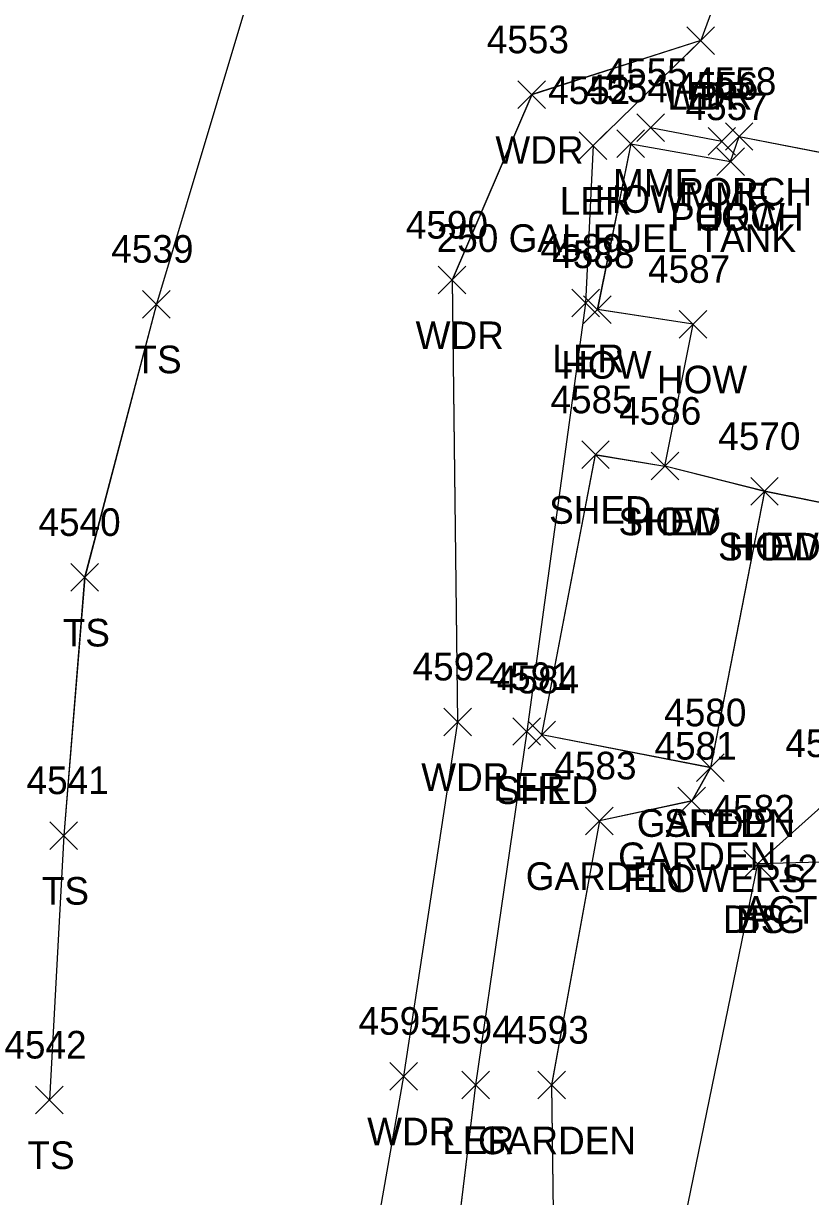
# Model space of a CAD drawing. Extents: x 1554668 to 1563881, y 831386 to 834374.
# Drawn here: x 1562370.9 to 1562427.9, y 833776.4 to 833861.3 of the extents above; entities that cross this region are included whole.
import ezdxf

# ---------------------------------------------------------------- set-up
doc = ezdxf.new("R2010")
doc.units = 0
for name, color, linetype in [('D_C', 7, 'Continuous'), ('L_A', 7, 'Continuous'), ('L_C', 7, 'Continuous'), ('L_I', 7, 'Continuous'), ('L_TIC', 7, 'Continuous'), ('LAPB', 7, 'Continuous'), ('LARO', 7, 'Continuous'), ('LAWA', 7, 'Continuous'), ('LBC', 7, 'Continuous'), ('LBF', 7, 'Continuous'), ('LDEFAULT', 7, 'Continuous'), ('LELB', 7, 'Continuous'), ('R_A', 7, 'Continuous'), ('R_I', 7, 'Continuous'), ('R_TIC', 7, 'Continuous'), ('RDG', 7, 'Continuous')]:
    doc.layers.add(name, color=color, linetype=linetype)

msp = doc.modelspace()

# ---------------------------------------------------------------- linework, layer by layer
at = {"layer": 'L_TIC'}
for points in [[(1562418.963, 833859.015), (1562420.963, 833861.015)], [(1562420.963, 833859.015), (1562418.963, 833861.015)], [(1562418.963, 833859.015), (1562420.963, 833861.015)], [(1562420.963, 833859.015), (1562418.963, 833861.015)], [(1562406.739, 833855.098), (1562408.739, 833857.098)], [(1562408.739, 833855.098), (1562406.739, 833857.098)], [(1562415.337, 833852.719), (1562417.337, 833854.719)], [(1562417.337, 833852.719), (1562415.337, 833854.719)], [(1562420.495, 833851.73), (1562422.495, 833853.73)], [(1562422.495, 833851.73), (1562420.495, 833853.73)], [(1562421.749, 833852.075), (1562423.749, 833854.075)], [(1562423.749, 833852.075), (1562421.749, 833854.075)], [(1562411.178, 833851.42), (1562413.178, 833853.42)], [(1562413.178, 833851.42), (1562411.178, 833853.42)], [(1562413.902, 833851.549), (1562415.902, 833853.549)], [(1562415.902, 833851.549), (1562413.902, 833853.549)], [(1562413.902, 833851.549), (1562415.902, 833853.549)], [(1562415.902, 833851.549), (1562413.902, 833853.549)], [(1562421.129, 833850.258), (1562423.129, 833852.258)], [(1562423.129, 833850.258), (1562421.129, 833852.258)], [(1562421.129, 833850.258), (1562423.129, 833852.258)], [(1562423.129, 833850.258), (1562421.129, 833852.258)], [(1562400.97, 833841.686), (1562402.97, 833843.686)], [(1562402.97, 833841.686), (1562400.97, 833843.686)], [(1562379.572, 833839.938), (1562381.572, 833841.938)], [(1562381.572, 833839.938), (1562379.572, 833841.938)], [(1562410.639, 833840.014), (1562412.639, 833842.014)], [(1562412.639, 833840.014), (1562410.639, 833842.014)], [(1562411.484, 833839.549), (1562413.484, 833841.549)], [(1562413.484, 833839.549), (1562411.484, 833841.549)], [(1562411.484, 833839.549), (1562413.484, 833841.549)], [(1562413.484, 833839.549), (1562411.484, 833841.549)], [(1562418.412, 833838.485), (1562420.412, 833840.485)], [(1562420.412, 833838.485), (1562418.412, 833840.485)], [(1562411.352, 833829.045), (1562413.352, 833831.045)], [(1562413.352, 833829.045), (1562411.352, 833831.045)], [(1562416.373, 833828.217), (1562418.373, 833830.217)], [(1562418.373, 833828.217), (1562416.373, 833830.217)], [(1562416.373, 833828.217), (1562418.373, 833830.217)], [(1562418.373, 833828.217), (1562416.373, 833830.217)], [(1562423.584, 833826.394), (1562425.584, 833828.394)], [(1562425.584, 833826.394), (1562423.584, 833828.394)], [(1562423.584, 833826.394), (1562425.584, 833828.394)], [(1562425.584, 833826.394), (1562423.584, 833828.394)], [(1562374.38, 833820.165), (1562376.38, 833822.165)], [(1562376.38, 833820.165), (1562374.38, 833822.165)], [(1562401.375, 833809.707), (1562403.375, 833811.707)], [(1562403.375, 833809.707), (1562401.375, 833811.707)], [(1562406.378, 833809.012), (1562408.378, 833811.012)], [(1562408.378, 833809.012), (1562406.378, 833811.012)], [(1562407.468, 833808.768), (1562409.468, 833810.768)], [(1562409.468, 833808.768), (1562407.468, 833810.768)], [(1562419.671, 833806.389), (1562421.671, 833808.389)], [(1562421.671, 833806.389), (1562419.671, 833808.389)], [(1562419.671, 833806.389), (1562421.671, 833808.389)], [(1562421.671, 833806.389), (1562419.671, 833808.389)], [(1562418.318, 833803.98), (1562420.318, 833805.98)], [(1562420.318, 833803.98), (1562418.318, 833805.98)], [(1562411.633, 833802.545), (1562413.633, 833804.545)], [(1562413.633, 833802.545), (1562411.633, 833804.545)], [(1562372.867, 833801.48), (1562374.867, 833803.48)], [(1562374.867, 833801.48), (1562372.867, 833803.48)], [(1562423.084, 833799.427), (1562425.084, 833801.427)], [(1562425.084, 833799.427), (1562423.084, 833801.427)], [(1562397.463, 833784.065), (1562399.463, 833786.065)], [(1562399.463, 833784.065), (1562397.463, 833786.065)], [(1562402.673, 833783.437), (1562404.673, 833785.437)], [(1562404.673, 833783.437), (1562402.673, 833785.437)], [(1562408.176, 833783.422), (1562410.176, 833785.422)], [(1562410.176, 833783.422), (1562408.176, 833785.422)], [(1562371.826, 833782.346), (1562373.826, 833784.346)], [(1562373.826, 833782.346), (1562371.826, 833784.346)]]:
    msp.add_lwpolyline(points, dxfattribs=at)
at = {"layer": 'LAPB'}
for points in [[(1562420.669, 833807.396), (1562419.316, 833804.986), (1562412.633, 833803.558), (1562409.177, 833784.435), (1562409.39, 833767.848), (1562405.557, 833759.29), (1562400.567, 833759.011)], [(1562420.669, 833807.396), (1562419.316, 833804.986), (1562412.633, 833803.558), (1562409.177, 833784.435), (1562409.39, 833767.848), (1562405.557, 833759.29), (1562400.567, 833759.011)], [(1562420.669, 833807.396), (1562419.316, 833804.986), (1562412.633, 833803.558), (1562409.177, 833784.435), (1562409.39, 833767.848), (1562405.557, 833759.29), (1562400.567, 833759.011)], [(1562420.671, 833807.389), (1562419.318, 833804.98), (1562412.633, 833803.545), (1562409.176, 833784.422), (1562409.391, 833767.84), (1562405.556, 833759.278), (1562400.568, 833759.003)]]:
    msp.add_lwpolyline(points, dxfattribs=at)
at = {"layer": 'LARO'}
for points in [[(1562419.963, 833860.015), (1562412.178, 833852.42), (1562411.639, 833841.014), (1562407.378, 833810.012), (1562403.673, 833784.437), (1562400.568, 833759.003), (1562399.074, 833758.901), (1562395.998, 833760.121), (1562387.534, 833736.965), (1562384.152, 833724.079), (1562381.399, 833714.569), (1562372.959, 833681.502), (1562364.479, 833661.333), (1562357.279, 833645.473), (1562345.403, 833619.618), (1562327.126, 833615.39), (1562315.305, 833599.808)], [(1562419.966, 833860.023), (1562412.181, 833852.429), (1562411.638, 833841.024), (1562407.377, 833810.024), (1562403.672, 833784.446), (1562400.567, 833759.011), (1562399.073, 833758.91), (1562395.997, 833760.128), (1562387.531, 833736.972), (1562384.152, 833724.088), (1562381.4, 833714.581), (1562372.955, 833681.511), (1562364.484, 833661.338), (1562357.283, 833645.478), (1562345.401, 833619.623), (1562327.128, 833615.397), (1562315.31, 833599.816)], [(1562419.966, 833860.023), (1562412.181, 833852.429), (1562411.638, 833841.024), (1562407.377, 833810.024), (1562403.672, 833784.446), (1562400.567, 833759.011), (1562399.073, 833758.91), (1562395.997, 833760.128), (1562387.531, 833736.972), (1562384.152, 833724.088), (1562381.4, 833714.581), (1562372.955, 833681.511), (1562364.484, 833661.338), (1562357.283, 833645.478), (1562345.401, 833619.623), (1562327.128, 833615.397), (1562315.31, 833599.816)], [(1562419.966, 833860.023), (1562412.181, 833852.429), (1562411.638, 833841.024), (1562407.377, 833810.024), (1562403.672, 833784.446), (1562400.567, 833759.011), (1562399.073, 833758.91), (1562395.997, 833760.128), (1562387.531, 833736.972), (1562384.152, 833724.088), (1562381.4, 833714.581), (1562372.955, 833681.511), (1562364.484, 833661.338), (1562357.283, 833645.478), (1562345.401, 833619.623), (1562327.128, 833615.397), (1562315.31, 833599.816)]]:
    msp.add_lwpolyline(points, dxfattribs=at)
at = {"layer": 'LAWA'}
for points in [[(1562378.208, 833932.425), (1562389.846, 833942.302), (1562394.252, 833938.943), (1562408.716, 833937.781), (1562415.125, 833914.02), (1562415.715, 833894.974), (1562418.032, 833878.589), (1562423.871, 833870.615), (1562419.966, 833860.023), (1562407.74, 833856.104), (1562401.969, 833842.691), (1562402.374, 833810.713), (1562398.461, 833785.078), (1562394.034, 833759.91)], [(1562378.208, 833932.425), (1562389.846, 833942.302), (1562394.252, 833938.943), (1562408.716, 833937.781), (1562415.125, 833914.02), (1562415.715, 833894.974), (1562418.032, 833878.589), (1562423.871, 833870.615), (1562419.966, 833860.023), (1562407.74, 833856.104), (1562401.969, 833842.691), (1562402.374, 833810.713), (1562398.461, 833785.078), (1562394.034, 833759.91)], [(1562378.208, 833932.425), (1562389.846, 833942.302), (1562394.252, 833938.943), (1562408.716, 833937.781), (1562415.125, 833914.02), (1562415.715, 833894.974), (1562418.032, 833878.589), (1562423.871, 833870.615), (1562419.966, 833860.023), (1562407.74, 833856.104), (1562401.969, 833842.691), (1562402.374, 833810.713), (1562398.461, 833785.078), (1562394.034, 833759.91)], [(1562378.208, 833932.42), (1562389.848, 833942.294), (1562394.25, 833938.94), (1562408.715, 833937.778), (1562415.128, 833914.011), (1562415.718, 833894.966), (1562418.033, 833878.583), (1562423.869, 833870.607), (1562419.963, 833860.015), (1562407.739, 833856.098), (1562401.97, 833842.686), (1562402.375, 833810.707), (1562398.463, 833785.065), (1562394.036, 833759.898)]]:
    msp.add_lwpolyline(points, dxfattribs=at)
at = {"layer": 'LBC'}
for points in [[(1562414.901, 833852.555), (1562412.483, 833840.561)], [(1562414.901, 833852.555), (1562412.483, 833840.561)], [(1562414.901, 833852.555), (1562412.483, 833840.561)], [(1562414.902, 833852.549), (1562412.484, 833840.549)], [(1562414.901, 833852.555), (1562422.132, 833851.267)], [(1562414.901, 833852.555), (1562422.132, 833851.267)], [(1562414.901, 833852.555), (1562422.132, 833851.267)], [(1562414.902, 833852.549), (1562422.129, 833851.258)], [(1562445.075, 833842.183), (1562441.39, 833824.008), (1562424.584, 833827.399), (1562417.372, 833829.227), (1562419.41, 833839.49), (1562412.483, 833840.561)], [(1562445.075, 833842.183), (1562441.39, 833824.008), (1562424.584, 833827.399), (1562417.372, 833829.227), (1562419.41, 833839.49), (1562412.483, 833840.561)], [(1562445.075, 833842.183), (1562441.39, 833824.008), (1562424.584, 833827.399), (1562417.372, 833829.227), (1562419.41, 833839.49), (1562412.483, 833840.561)], [(1562445.076, 833842.176), (1562441.389, 833824.003), (1562424.584, 833827.394), (1562417.373, 833829.217), (1562419.412, 833839.485), (1562412.484, 833840.549)], [(1562424.584, 833827.399), (1562420.669, 833807.396), (1562408.466, 833809.775), (1562412.35, 833830.05), (1562417.372, 833829.227)], [(1562424.584, 833827.399), (1562420.669, 833807.396), (1562408.466, 833809.775), (1562412.35, 833830.05), (1562417.372, 833829.227)], [(1562424.584, 833827.399), (1562420.669, 833807.396), (1562408.466, 833809.775), (1562412.35, 833830.05), (1562417.372, 833829.227)], [(1562424.584, 833827.394), (1562420.671, 833807.389), (1562408.468, 833809.768), (1562412.352, 833830.045), (1562417.373, 833829.217)]]:
    msp.add_lwpolyline(points, dxfattribs=at)
at = {"layer": 'LBF'}
for points in [[(1562422.129, 833851.258), (1562422.749, 833853.075), (1562435.102, 833850.67), (1562440.566, 833849.466), (1562446.365, 833848.39), (1562445.076, 833842.176)], [(1562422.132, 833851.267), (1562422.749, 833853.081), (1562435.102, 833850.678), (1562440.566, 833849.476), (1562446.364, 833848.399), (1562445.075, 833842.183)], [(1562422.132, 833851.267), (1562422.749, 833853.081), (1562435.102, 833850.678), (1562440.566, 833849.476), (1562446.364, 833848.399), (1562445.075, 833842.183)], [(1562422.132, 833851.267), (1562422.749, 833853.081), (1562435.102, 833850.678), (1562440.566, 833849.476), (1562446.364, 833848.399), (1562445.075, 833842.183)]]:
    msp.add_lwpolyline(points, dxfattribs=at)
at = {"layer": 'LDEFAULT'}
for points in [[(1562416.337, 833853.726), (1562421.497, 833852.739)], [(1562416.337, 833853.726), (1562421.497, 833852.739)], [(1562416.337, 833853.726), (1562421.497, 833852.739)], [(1562416.337, 833853.719), (1562421.495, 833852.73)]]:
    msp.add_lwpolyline(points, dxfattribs=at)
at = {"layer": 'LELB'}
for points in [[(1562394.252, 833938.943), (1562392.007, 833921.885), (1562390.327, 833902.359), (1562390.311, 833886.596), (1562389.314, 833870.102), (1562380.568, 833840.943), (1562375.377, 833821.168), (1562373.869, 833802.489), (1562372.825, 833783.352)], [(1562394.252, 833938.943), (1562392.007, 833921.885), (1562390.327, 833902.359), (1562390.311, 833886.596), (1562389.314, 833870.102), (1562380.568, 833840.943), (1562375.377, 833821.168), (1562373.869, 833802.489), (1562372.825, 833783.352)], [(1562394.252, 833938.943), (1562392.007, 833921.885), (1562390.327, 833902.359), (1562390.311, 833886.596), (1562389.314, 833870.102), (1562380.568, 833840.943), (1562375.377, 833821.168), (1562373.869, 833802.489), (1562372.825, 833783.352)], [(1562394.25, 833938.94), (1562392.008, 833921.878), (1562390.329, 833902.353), (1562390.308, 833886.591), (1562389.311, 833870.096), (1562380.572, 833840.938), (1562375.38, 833821.165), (1562373.867, 833802.48), (1562372.826, 833783.346)], [(1562434.776, 833807.902), (1562429.358, 833805.169), (1562424.083, 833800.435)], [(1562434.776, 833807.902), (1562429.358, 833805.169), (1562424.083, 833800.435)], [(1562434.776, 833807.902), (1562429.358, 833805.169), (1562424.083, 833800.435)], [(1562434.776, 833807.899), (1562429.359, 833805.16), (1562424.084, 833800.427)]]:
    msp.add_lwpolyline(points, dxfattribs=at)
at = {"layer": 'R_TIC'}
for points in [[(1562423.084, 833799.427), (1562425.084, 833801.427)], [(1562425.084, 833799.427), (1562423.084, 833801.427)]]:
    msp.add_lwpolyline(points, dxfattribs=at)
at = {"layer": 'RDG'}
for points in [[(1562446.514, 833813.563), (1562443.872, 833811.177), (1562440.454, 833805.407), (1562432.393, 833800.653), (1562424.083, 833800.435), (1562417.273, 833767.263), (1562421.889, 833758.153), (1562425.326, 833750.474), (1562429.669, 833734.264)], [(1562446.514, 833813.563), (1562443.872, 833811.177), (1562440.454, 833805.407), (1562432.393, 833800.653), (1562424.083, 833800.435), (1562417.273, 833767.263), (1562421.889, 833758.153), (1562425.326, 833750.474), (1562429.669, 833734.264)], [(1562446.514, 833813.563), (1562443.872, 833811.177), (1562440.454, 833805.407), (1562432.393, 833800.653), (1562424.083, 833800.435), (1562417.273, 833767.263), (1562421.889, 833758.153), (1562425.326, 833750.474), (1562429.669, 833734.264)], [(1562446.513, 833813.556), (1562443.872, 833811.172), (1562440.453, 833805.4), (1562432.393, 833800.647), (1562424.084, 833800.427), (1562417.274, 833767.254), (1562421.893, 833758.146), (1562425.324, 833750.465), (1562429.671, 833734.255)]]:
    msp.add_lwpolyline(points, dxfattribs=at)

# ---------------------------------------------------------------- texts
at = {"layer": 'D_C'}
for s, p in [('12" VERTICAL CIP', (1562425.486, 833799.096)), ('ACTUAL SIZE OF DI', (1562423.068, 833796.096))]:
    msp.add_text(s, height=2, dxfattribs=at).set_placement(p)
at = {"layer": 'L_A'}
for s, p in [('WDR', (1562417.326, 833855.015)), ('LER', (1562417.546, 833855.015)), ('WDR', (1562405.101, 833851.098)), ('MMF', (1562413.62, 833848.719)), ('HOW', (1562412.288, 833847.549)), ('HOW', (1562412.288, 833847.549)), ('PORCH', (1562418.371, 833848.075)), ('MMF', (1562418.778, 833847.73)), ('LER', (1562409.761, 833847.42)), ('PORCH', (1562417.751, 833846.258)), ('HOW', (1562419.515, 833846.258)), ('WDR', (1562399.332, 833837.686)), ('TS', (1562378.981, 833835.938)), ('LER', (1562409.222, 833836.014)), ('HOW', (1562409.87, 833835.549)), ('HOW', (1562409.87, 833835.549)), ('HOW', (1562416.798, 833834.485)), ('SHED', (1562408.99, 833825.045)), ('SHED', (1562414.011, 833824.217)), ('HOW', (1562414.759, 833824.217)), ('SHED', (1562421.222, 833822.394)), ('HOW', (1562421.97, 833822.394)), ('TS', (1562373.79, 833816.165)), ('WDR', (1562399.737, 833805.707)), ('LER', (1562404.961, 833805.012)), ('SHED', (1562405.105, 833804.768)), ('GARDEN', (1562415.34, 833802.389)), ('SHED', (1562417.308, 833802.389)), ('GARDEN', (1562413.987, 833799.98)), ('GARDEN', (1562407.303, 833798.545)), ('TS', (1562372.276, 833797.48)), ('BS', (1562422.525, 833795.427)), ('WDR', (1562395.825, 833780.065)), ('LER', (1562401.256, 833779.437)), ('GARDEN', (1562403.846, 833779.422)), ('TS', (1562371.235, 833778.346))]:
    msp.add_text(s, height=2, dxfattribs=at).set_placement(p)
at = {"layer": 'L_C'}
for s, p in [('250 GAL FUEL TANK', (1562400.856, 833844.719)), ('FLOWERS', (1562414.371, 833798.389))]:
    msp.add_text(s, height=2, dxfattribs=at).set_placement(p)
at = {"layer": 'L_I'}
for s, p in [('4553', (1562404.479, 833859.098)), ('4555', (1562413.077, 833856.719)), ('4558', (1562419.489, 833856.075)), ('4552', (1562408.918, 833855.42)), ('4554', (1562411.642, 833855.549)), ('4554', (1562411.642, 833855.549)), ('4556', (1562418.18, 833855.73)), ('4557', (1562418.869, 833854.258)), ('4557', (1562418.869, 833854.258)), ('4590', (1562398.624, 833845.686)), ('4539', (1562377.304, 833843.938)), ('4589', (1562408.371, 833844.014)), ('4588', (1562409.224, 833843.549)), ('4588', (1562409.224, 833843.549)), ('4587', (1562416.152, 833842.485)), ('4585', (1562409.092, 833833.045)), ('4586', (1562414.058, 833832.217)), ('4586', (1562414.058, 833832.217)), ('4570', (1562421.238, 833830.394)), ('4570', (1562421.238, 833830.394)), ('4540', (1562372.034, 833824.165)), ('4592', (1562399.115, 833813.707)), ('4591', (1562404.685, 833813.012)), ('4584', (1562405.208, 833812.768)), ('4580', (1562417.324, 833810.389)), ('4580', (1562417.324, 833810.389)), ('4581', (1562416.625, 833807.98)), ('4579', (1562426.091, 833808.16)), ('4583', (1562409.373, 833806.545)), ('4541', (1562371.174, 833805.48)), ('4582', (1562420.824, 833803.427)), ('4595', (1562395.203, 833788.065)), ('4594', (1562400.413, 833787.437)), ('4593', (1562405.917, 833787.422)), ('4542', (1562369.566, 833786.346))]:
    msp.add_text(s, height=2, dxfattribs=at).set_placement(p)
at = {"layer": 'R_A'}
msp.add_text('DRG', height=2, dxfattribs=at).set_placement((1562421.572, 833795.427))
at = {"layer": 'R_I'}
msp.add_text('4582', height=2, dxfattribs=at).set_placement((1562420.824, 833803.427))

doc.saveas('drawing.dxf')
